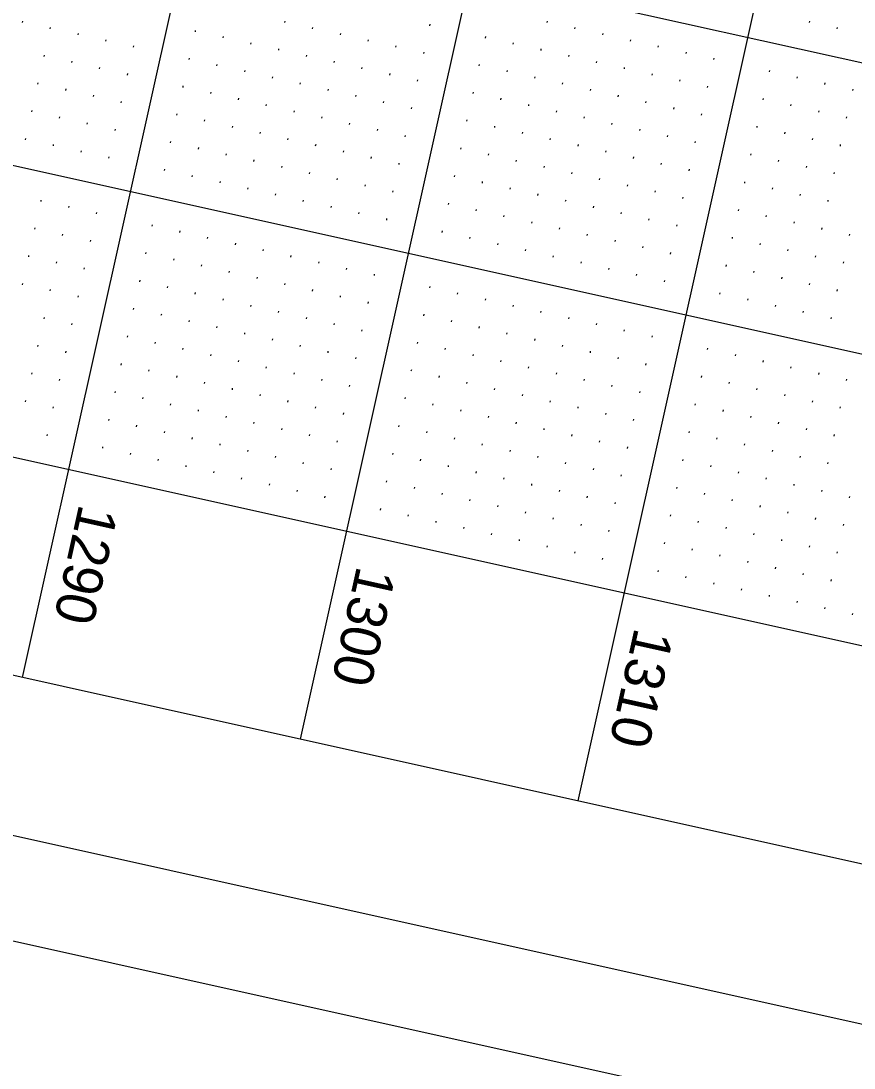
# Model space of a CAD drawing. Extents: x 2149268 to 2150830, y 142155 to 144285.
# Drawn here: x 2149571.9 to 2149718.3, y 142325.7 to 142509.8 of the extents above; entities that cross this region are included whole.
import ezdxf

# ---------------------------------------------------------------- set-up
doc = ezdxf.new("R2010")
doc.units = 0
for name, color, linetype in [('SHT_Plan_Profile_Sheet_Elev_Txt', 7, 'Continuous'), ('SHT_Plot_Shape_Full', 7, 'Continuous'), ('SHT_Plot_Shape_Half', 7, 'Continuous'), ('SHT_Profile_Grid_Major', 7, 'Continuous'), ('SHT_Profile_Grid_Minor', 7, 'Continuous'), ('SHT_Sheet_Border', 7, 'Continuous')]:
    doc.layers.add(name, color=color, linetype=linetype)

msp = doc.modelspace()

# ---------------------------------------------------------------- linework, layer by layer
at = {"layer": 'SHT_Plot_Shape_Full'}
msp.add_lwpolyline([(2150830.28, 143911.83), (2150439.58, 142154.75), (2149268.19, 142415.21), (2149658.89, 144172.3)], close=True, dxfattribs=at)
at = {"layer": 'SHT_Plot_Shape_Half'}
msp.add_lwpolyline([(2150772.24, 143840.86), (2150403.25, 142181.39), (2149329.47, 142420.15), (2149698.47, 144079.62)], close=True, dxfattribs=at)
at = {"layer": 'SHT_Profile_Grid_Major'}
for p, q in [((2149914.02, 143931.81), (2149572.16, 142394.36)), ((2149962.83, 143920.96), (2149620.97, 142383.51)), ((2150011.64, 143910.11), (2149669.77, 142372.66)), ((2149504.39, 142550.29), (2149894.85, 142463.47)), ((2149493.54, 142501.48), (2149884, 142414.66))]:
    msp.add_line(p, q, dxfattribs=at)
at = {"layer": 'SHT_Profile_Grid_Minor'}
for p, q in [((2149572.2, 142509.73), (2149572.15, 142509.48)), ((2149577.08, 142508.64), (2149577.03, 142508.4)), ((2149602.57, 142508.1), (2149602.52, 142507.85)), ((2149618.3, 142509.72), (2149618.24, 142509.48)), ((2149623.18, 142508.64), (2149623.13, 142508.39)), ((2149643.79, 142509.18), (2149643.73, 142508.93)), ((2149664.4, 142509.72), (2149664.34, 142509.47)), ((2149669.28, 142508.63), (2149669.22, 142508.39)), ((2149710.49, 142509.71), (2149710.44, 142509.47)), ((2149715.37, 142508.62), (2149715.32, 142508.38)), ((2149581.96, 142507.56), (2149581.91, 142507.31)), ((2149586.84, 142506.47), (2149586.79, 142506.23)), ((2149607.45, 142507.01), (2149607.4, 142506.77)), ((2149628.06, 142507.55), (2149628.01, 142507.31)), ((2149632.94, 142506.47), (2149632.89, 142506.22)), ((2149653.55, 142507.01), (2149653.5, 142506.76)), ((2149674.16, 142507.55), (2149674.1, 142507.3)), ((2149679.04, 142506.46), (2149678.98, 142506.22)), ((2149591.72, 142505.39), (2149591.67, 142505.14)), ((2149612.33, 142505.93), (2149612.28, 142505.68)), ((2149617.21, 142504.84), (2149617.16, 142504.6)), ((2149637.82, 142505.38), (2149637.77, 142505.14)), ((2149642.7, 142504.3), (2149642.65, 142504.05)), ((2149658.43, 142505.92), (2149658.38, 142505.68)), ((2149663.31, 142504.84), (2149663.26, 142504.59)), ((2149683.92, 142505.37), (2149683.87, 142505.13)), ((2149688.8, 142504.29), (2149688.75, 142504.05)), ((2149576, 142503.76), (2149575.94, 142503.52)), ((2149580.88, 142502.68), (2149580.82, 142502.43)), ((2149601.49, 142503.22), (2149601.43, 142502.97)), ((2149622.09, 142503.76), (2149622.04, 142503.51)), ((2149626.97, 142502.67), (2149626.92, 142502.43)), ((2149668.19, 142503.75), (2149668.14, 142503.51)), ((2149673.07, 142502.66), (2149673.02, 142502.42)), ((2149693.68, 142503.2), (2149693.63, 142502.96)), ((2149585.76, 142501.59), (2149585.7, 142501.35)), ((2149606.37, 142502.13), (2149606.31, 142501.89)), ((2149611.25, 142501.05), (2149611.19, 142500.8)), ((2149631.86, 142501.59), (2149631.8, 142501.34)), ((2149652.46, 142502.13), (2149652.41, 142501.88)), ((2149657.35, 142501.04), (2149657.29, 142500.8)), ((2149677.95, 142501.58), (2149677.9, 142501.34)), ((2149703.44, 142501.03), (2149703.39, 142500.79)), ((2149574.91, 142498.88), (2149574.86, 142498.64)), ((2149590.64, 142500.51), (2149590.58, 142500.26)), ((2149616.13, 142499.96), (2149616.07, 142499.72)), ((2149621.01, 142498.88), (2149620.95, 142498.63)), ((2149636.74, 142500.5), (2149636.68, 142500.26)), ((2149641.62, 142499.41), (2149641.56, 142499.17)), ((2149662.23, 142499.95), (2149662.17, 142499.71)), ((2149667.11, 142498.87), (2149667.05, 142498.63)), ((2149682.83, 142500.49), (2149682.78, 142500.25)), ((2149687.72, 142499.41), (2149687.66, 142499.16)), ((2149708.32, 142499.95), (2149708.27, 142499.7)), ((2149713.2, 142498.86), (2149713.15, 142498.62)), ((2149579.79, 142497.8), (2149579.74, 142497.55)), ((2149600.4, 142498.34), (2149600.35, 142498.09)), ((2149605.28, 142497.25), (2149605.23, 142497.01)), ((2149625.89, 142497.79), (2149625.84, 142497.55)), ((2149651.38, 142497.24), (2149651.32, 142497)), ((2149671.99, 142497.78), (2149671.93, 142497.54)), ((2149692.6, 142498.32), (2149692.54, 142498.08)), ((2149718.09, 142497.78), (2149718.03, 142497.53)), ((2149584.67, 142496.71), (2149584.62, 142496.47)), ((2149589.55, 142495.63), (2149589.5, 142495.38)), ((2149610.16, 142496.16), (2149610.11, 142495.92)), ((2149615.04, 142495.08), (2149614.99, 142494.84)), ((2149630.77, 142496.7), (2149630.72, 142496.46)), ((2149635.65, 142495.62), (2149635.6, 142495.38)), ((2149656.26, 142496.16), (2149656.21, 142495.91)), ((2149661.14, 142495.07), (2149661.09, 142494.83)), ((2149676.87, 142496.7), (2149676.81, 142496.45)), ((2149681.75, 142495.61), (2149681.69, 142495.37)), ((2149702.36, 142496.15), (2149702.3, 142495.91)), ((2149707.24, 142495.07), (2149707.18, 142494.82)), ((2149573.83, 142494), (2149573.77, 142493.76)), ((2149599.32, 142493.45), (2149599.26, 142493.21)), ((2149619.92, 142493.99), (2149619.87, 142493.75)), ((2149640.53, 142494.53), (2149640.48, 142494.29)), ((2149666.02, 142493.99), (2149665.97, 142493.74)), ((2149686.63, 142494.53), (2149686.58, 142494.28)), ((2149691.51, 142493.44), (2149691.46, 142493.2)), ((2149712.12, 142493.98), (2149712.06, 142493.74)), ((2149578.71, 142492.92), (2149578.65, 142492.67)), ((2149583.59, 142491.83), (2149583.53, 142491.59)), ((2149604.2, 142492.37), (2149604.14, 142492.13)), ((2149624.8, 142492.91), (2149624.75, 142492.67)), ((2149629.69, 142491.82), (2149629.63, 142491.58)), ((2149650.29, 142492.36), (2149650.24, 142492.12)), ((2149670.9, 142492.9), (2149670.85, 142492.66)), ((2149675.78, 142491.82), (2149675.73, 142491.57)), ((2149717, 142492.9), (2149716.95, 142492.65)), ((2149588.47, 142490.74), (2149588.41, 142490.5)), ((2149609.08, 142491.28), (2149609.02, 142491.04)), ((2149613.96, 142490.2), (2149613.9, 142489.95)), ((2149634.57, 142490.74), (2149634.51, 142490.49)), ((2149639.45, 142489.65), (2149639.39, 142489.41)), ((2149655.17, 142491.28), (2149655.12, 142491.03)), ((2149660.06, 142490.19), (2149660, 142489.95)), ((2149680.66, 142490.73), (2149680.61, 142490.49)), ((2149685.54, 142489.65), (2149685.49, 142489.4)), ((2149701.27, 142491.27), (2149701.22, 142491.03)), ((2149706.15, 142490.19), (2149706.1, 142489.94)), ((2149572.74, 142489.12), (2149572.69, 142488.88)), ((2149577.62, 142488.03), (2149577.57, 142487.79)), ((2149598.23, 142488.57), (2149598.18, 142488.33)), ((2149618.84, 142489.11), (2149618.78, 142488.87)), ((2149623.72, 142488.03), (2149623.66, 142487.78)), ((2149664.94, 142489.11), (2149664.88, 142488.86)), ((2149669.82, 142488.02), (2149669.76, 142487.78)), ((2149690.43, 142488.56), (2149690.37, 142488.32)), ((2149711.03, 142489.1), (2149710.98, 142488.86)), ((2149715.91, 142488.02), (2149715.86, 142487.77)), ((2149582.5, 142486.95), (2149582.45, 142486.7)), ((2149587.38, 142485.86), (2149587.33, 142485.62)), ((2149603.11, 142487.49), (2149603.06, 142487.24)), ((2149607.99, 142486.4), (2149607.94, 142486.16)), ((2149628.6, 142486.94), (2149628.55, 142486.7)), ((2149633.48, 142485.86), (2149633.43, 142485.61)), ((2149649.21, 142487.48), (2149649.15, 142487.24)), ((2149654.09, 142486.4), (2149654.03, 142486.15)), ((2149674.7, 142486.94), (2149674.64, 142486.69)), ((2149679.58, 142485.85), (2149679.52, 142485.61)), ((2149700.19, 142486.39), (2149700.13, 142486.15)), ((2149612.87, 142485.32), (2149612.82, 142485.07)), ((2149617.75, 142484.23), (2149617.7, 142483.99)), ((2149638.36, 142484.77), (2149638.31, 142484.53)), ((2149658.97, 142485.31), (2149658.92, 142485.07)), ((2149663.85, 142484.23), (2149663.8, 142483.98)), ((2149684.46, 142484.77), (2149684.4, 142484.52)), ((2149705.07, 142485.31), (2149705.01, 142485.06)), ((2149709.95, 142484.22), (2149709.89, 142483.98)), ((2149597.14, 142483.69), (2149597.09, 142483.45)), ((2149602.03, 142482.61), (2149601.97, 142482.36)), ((2149622.63, 142483.15), (2149622.58, 142482.9)), ((2149648.12, 142482.6), (2149648.07, 142482.36)), ((2149668.73, 142483.14), (2149668.68, 142482.9)), ((2149689.34, 142483.68), (2149689.29, 142483.44)), ((2149714.83, 142483.14), (2149714.78, 142482.89)), ((2149606.91, 142481.52), (2149606.85, 142481.28)), ((2149611.79, 142480.44), (2149611.73, 142480.19)), ((2149627.51, 142482.06), (2149627.46, 142481.82)), ((2149632.4, 142480.98), (2149632.34, 142480.73)), ((2149653, 142481.52), (2149652.95, 142481.27)), ((2149657.88, 142480.43), (2149657.83, 142480.19)), ((2149673.61, 142482.06), (2149673.56, 142481.81)), ((2149678.49, 142480.97), (2149678.44, 142480.73)), ((2149699.1, 142481.51), (2149699.05, 142481.27)), ((2149703.98, 142480.43), (2149703.93, 142480.18)), ((2149616.67, 142479.35), (2149616.61, 142479.11)), ((2149637.28, 142479.89), (2149637.22, 142479.65)), ((2149662.77, 142479.35), (2149662.71, 142479.1)), ((2149683.37, 142479.89), (2149683.32, 142479.64)), ((2149688.25, 142478.8), (2149688.2, 142478.56)), ((2149708.86, 142479.34), (2149708.81, 142479.1)), ((2149575.45, 142478.27), (2149575.4, 142478.03)), ((2149580.33, 142477.19), (2149580.28, 142476.94)), ((2149621.55, 142478.27), (2149621.49, 142478.02)), ((2149626.43, 142477.18), (2149626.38, 142476.94)), ((2149647.04, 142477.72), (2149646.98, 142477.48)), ((2149667.65, 142478.26), (2149667.59, 142478.02)), ((2149672.53, 142477.18), (2149672.47, 142476.93)), ((2149713.74, 142478.25), (2149713.69, 142478.01)), ((2149585.21, 142476.1), (2149585.16, 142475.86)), ((2149631.31, 142476.1), (2149631.26, 142475.85)), ((2149636.19, 142475.01), (2149636.14, 142474.77)), ((2149651.92, 142476.64), (2149651.86, 142476.39)), ((2149656.8, 142475.55), (2149656.75, 142475.31)), ((2149677.41, 142476.09), (2149677.35, 142475.85)), ((2149682.29, 142475), (2149682.23, 142474.76)), ((2149698.02, 142476.63), (2149697.96, 142476.39)), ((2149702.9, 142475.54), (2149702.84, 142475.3)), ((2149574.37, 142473.39), (2149574.31, 142473.15)), ((2149594.97, 142473.93), (2149594.92, 142473.69)), ((2149661.68, 142474.47), (2149661.63, 142474.22)), ((2149666.56, 142473.38), (2149666.51, 142473.14)), ((2149687.17, 142473.92), (2149687.12, 142473.68)), ((2149707.78, 142474.46), (2149707.72, 142474.22)), ((2149712.66, 142473.37), (2149712.6, 142473.13)), ((2149579.25, 142472.31), (2149579.19, 142472.06)), ((2149584.13, 142471.22), (2149584.07, 142470.98)), ((2149599.85, 142472.85), (2149599.8, 142472.6)), ((2149604.74, 142471.76), (2149604.68, 142471.52)), ((2149645.95, 142472.84), (2149645.9, 142472.6)), ((2149650.83, 142471.76), (2149650.78, 142471.51)), ((2149671.44, 142472.29), (2149671.39, 142472.05)), ((2149676.32, 142471.21), (2149676.27, 142470.97)), ((2149696.93, 142471.75), (2149696.88, 142471.51)), ((2149717.54, 142472.29), (2149717.49, 142472.04)), ((2149609.62, 142470.68), (2149609.56, 142470.43)), ((2149614.5, 142469.59), (2149614.44, 142469.35)), ((2149655.71, 142470.67), (2149655.66, 142470.43)), ((2149660.59, 142469.58), (2149660.54, 142469.34)), ((2149681.2, 142470.12), (2149681.15, 142469.88)), ((2149701.81, 142470.66), (2149701.76, 142470.42)), ((2149706.69, 142469.58), (2149706.64, 142469.33)), ((2149573.28, 142468.51), (2149573.23, 142468.27)), ((2149593.89, 142469.05), (2149593.83, 142468.81)), ((2149598.77, 142467.97), (2149598.72, 142467.72)), ((2149619.38, 142468.51), (2149619.32, 142468.26)), ((2149665.48, 142468.5), (2149665.42, 142468.26)), ((2149686.08, 142469.04), (2149686.03, 142468.79)), ((2149711.57, 142468.49), (2149711.52, 142468.25)), ((2149578.16, 142467.43), (2149578.11, 142467.18)), ((2149583.04, 142466.34), (2149582.99, 142466.1)), ((2149603.65, 142466.88), (2149603.6, 142466.64)), ((2149608.53, 142465.79), (2149608.48, 142465.55)), ((2149624.26, 142467.42), (2149624.2, 142467.18)), ((2149629.14, 142466.33), (2149629.09, 142466.09)), ((2149670.36, 142467.41), (2149670.3, 142467.17)), ((2149675.24, 142466.33), (2149675.18, 142466.08)), ((2149695.85, 142466.87), (2149695.79, 142466.62)), ((2149700.73, 142465.78), (2149700.67, 142465.54)), ((2149716.45, 142467.41), (2149716.4, 142467.16)), ((2149592.8, 142464.17), (2149592.75, 142463.93)), ((2149613.41, 142464.71), (2149613.36, 142464.47)), ((2149634.02, 142465.25), (2149633.97, 142465.01)), ((2149680.12, 142465.24), (2149680.06, 142465)), ((2149685, 142464.16), (2149684.94, 142463.91)), ((2149705.61, 142464.7), (2149705.55, 142464.45)), ((2149572.19, 142463.63), (2149572.14, 142463.39)), ((2149577.08, 142462.54), (2149577.02, 142462.3)), ((2149597.68, 142463.08), (2149597.63, 142462.84)), ((2149602.57, 142462), (2149602.51, 142461.76)), ((2149618.29, 142463.62), (2149618.24, 142463.38)), ((2149623.17, 142462.54), (2149623.12, 142462.29)), ((2149643.78, 142463.08), (2149643.73, 142462.83)), ((2149648.66, 142461.99), (2149648.61, 142461.75)), ((2149694.76, 142461.99), (2149694.71, 142461.74)), ((2149710.49, 142463.61), (2149710.43, 142463.37)), ((2149715.37, 142462.53), (2149715.31, 142462.28)), ((2149581.96, 142461.46), (2149581.9, 142461.22)), ((2149607.45, 142460.91), (2149607.39, 142460.67)), ((2149628.05, 142461.45), (2149628, 142461.21)), ((2149632.94, 142460.37), (2149632.88, 142460.12)), ((2149653.54, 142460.91), (2149653.49, 142460.66)), ((2149699.64, 142460.9), (2149699.59, 142460.66)), ((2149591.72, 142459.29), (2149591.66, 142459.05)), ((2149612.33, 142459.83), (2149612.27, 142459.58)), ((2149617.21, 142458.74), (2149617.15, 142458.5)), ((2149658.42, 142459.82), (2149658.37, 142459.58)), ((2149663.31, 142458.74), (2149663.25, 142458.49)), ((2149704.52, 142459.82), (2149704.47, 142459.57)), ((2149709.4, 142458.73), (2149709.35, 142458.49)), ((2149575.99, 142457.66), (2149575.94, 142457.42)), ((2149580.87, 142456.58), (2149580.82, 142456.33)), ((2149596.6, 142458.2), (2149596.54, 142457.96)), ((2149601.48, 142457.12), (2149601.43, 142456.87)), ((2149622.09, 142457.66), (2149622.03, 142457.41)), ((2149626.97, 142456.57), (2149626.91, 142456.33)), ((2149642.7, 142458.2), (2149642.64, 142457.95)), ((2149647.58, 142457.11), (2149647.52, 142456.87)), ((2149668.19, 142457.65), (2149668.13, 142457.41)), ((2149673.07, 142456.57), (2149673.01, 142456.32)), ((2149714.28, 142457.65), (2149714.23, 142457.4)), ((2149606.36, 142456.03), (2149606.31, 142455.79)), ((2149611.24, 142454.95), (2149611.19, 142454.7)), ((2149631.85, 142455.49), (2149631.8, 142455.24)), ((2149652.46, 142456.03), (2149652.4, 142455.78)), ((2149657.34, 142454.94), (2149657.28, 142454.7)), ((2149677.95, 142455.48), (2149677.89, 142455.24)), ((2149574.91, 142452.78), (2149574.85, 142452.54)), ((2149590.63, 142454.41), (2149590.58, 142454.16)), ((2149595.51, 142453.32), (2149595.46, 142453.08)), ((2149616.12, 142453.86), (2149616.07, 142453.62)), ((2149621, 142452.78), (2149620.95, 142452.53)), ((2149641.61, 142453.32), (2149641.56, 142453.07)), ((2149662.22, 142453.86), (2149662.17, 142453.61)), ((2149667.1, 142452.77), (2149667.05, 142452.53)), ((2149682.83, 142454.4), (2149682.77, 142454.15)), ((2149579.79, 142451.7), (2149579.73, 142451.45)), ((2149600.39, 142452.24), (2149600.34, 142451.99)), ((2149605.28, 142451.15), (2149605.22, 142450.91)), ((2149625.88, 142451.69), (2149625.83, 142451.45)), ((2149646.49, 142452.23), (2149646.44, 142451.99)), ((2149651.37, 142451.15), (2149651.32, 142450.9)), ((2149671.98, 142451.69), (2149671.93, 142451.44)), ((2149692.59, 142452.23), (2149692.54, 142451.98)), ((2149697.47, 142451.14), (2149697.42, 142450.9)), ((2149589.55, 142449.53), (2149589.49, 142449.28)), ((2149610.16, 142450.07), (2149610.1, 142449.82)), ((2149630.76, 142450.61), (2149630.71, 142450.36)), ((2149656.25, 142450.06), (2149656.2, 142449.82)), ((2149676.86, 142450.6), (2149676.81, 142450.36)), ((2149681.74, 142449.52), (2149681.69, 142449.27)), ((2149702.35, 142450.06), (2149702.3, 142449.81)), ((2149573.82, 142447.9), (2149573.77, 142447.66)), ((2149594.43, 142448.44), (2149594.37, 142448.2)), ((2149599.31, 142447.36), (2149599.25, 142447.11)), ((2149615.04, 142448.98), (2149614.98, 142448.74)), ((2149619.92, 142447.9), (2149619.86, 142447.65)), ((2149640.53, 142448.44), (2149640.47, 142448.19)), ((2149645.41, 142447.35), (2149645.35, 142447.11)), ((2149661.13, 142448.98), (2149661.08, 142448.73)), ((2149666.02, 142447.89), (2149665.96, 142447.65)), ((2149691.5, 142447.35), (2149691.45, 142447.1)), ((2149707.23, 142448.97), (2149707.18, 142448.73)), ((2149712.11, 142447.88), (2149712.06, 142447.64)), ((2149578.7, 142446.82), (2149578.65, 142446.57)), ((2149604.19, 142446.27), (2149604.14, 142446.03)), ((2149624.8, 142446.81), (2149624.74, 142446.57)), ((2149629.68, 142445.73), (2149629.62, 142445.48)), ((2149650.29, 142446.27), (2149650.23, 142446.02)), ((2149670.9, 142446.81), (2149670.84, 142446.56)), ((2149675.78, 142445.72), (2149675.72, 142445.48)), ((2149696.39, 142446.26), (2149696.33, 142446.02)), ((2149716.99, 142446.8), (2149716.94, 142446.56)), ((2149588.46, 142444.65), (2149588.41, 142444.4)), ((2149593.34, 142443.56), (2149593.29, 142443.32)), ((2149609.07, 142445.19), (2149609.02, 142444.94)), ((2149613.95, 142444.1), (2149613.9, 142443.86)), ((2149639.44, 142443.56), (2149639.39, 142443.31)), ((2149655.17, 142445.18), (2149655.11, 142444.94)), ((2149660.05, 142444.1), (2149660, 142443.85)), ((2149680.66, 142444.63), (2149680.6, 142444.39)), ((2149701.27, 142445.17), (2149701.21, 142444.93)), ((2149706.15, 142444.09), (2149706.09, 142443.85)), ((2149572.73, 142443.02), (2149572.68, 142442.78)), ((2149577.62, 142441.94), (2149577.56, 142441.69)), ((2149598.22, 142442.48), (2149598.17, 142442.23)), ((2149618.83, 142443.02), (2149618.78, 142442.77)), ((2149623.71, 142441.93), (2149623.66, 142441.69)), ((2149644.32, 142442.47), (2149644.27, 142442.23)), ((2149664.93, 142443.01), (2149664.88, 142442.77)), ((2149669.81, 142441.92), (2149669.76, 142441.68)), ((2149690.42, 142442.46), (2149690.37, 142442.22)), ((2149711.03, 142443), (2149710.97, 142442.76)), ((2149715.91, 142441.92), (2149715.85, 142441.67)), ((2149603.1, 142441.39), (2149603.05, 142441.15)), ((2149607.99, 142440.31), (2149607.93, 142440.06)), ((2149628.59, 142440.85), (2149628.54, 142440.6)), ((2149649.2, 142441.38), (2149649.15, 142441.14)), ((2149654.08, 142440.3), (2149654.03, 142440.06)), ((2149674.69, 142440.84), (2149674.64, 142440.6)), ((2149695.3, 142441.38), (2149695.25, 142441.13)), ((2149700.18, 142440.29), (2149700.13, 142440.05)), ((2149587.38, 142439.77), (2149587.32, 142439.52)), ((2149592.26, 142438.68), (2149592.2, 142438.44)), ((2149612.87, 142439.22), (2149612.81, 142438.98)), ((2149617.75, 142438.14), (2149617.69, 142437.89)), ((2149638.36, 142438.67), (2149638.3, 142438.43)), ((2149658.96, 142439.21), (2149658.91, 142438.97)), ((2149663.84, 142438.13), (2149663.79, 142437.89)), ((2149679.57, 142439.75), (2149679.52, 142439.51)), ((2149705.06, 142439.21), (2149705.01, 142438.96)), ((2149709.94, 142438.12), (2149709.89, 142437.88)), ((2149576.53, 142437.06), (2149576.48, 142436.81)), ((2149597.14, 142437.6), (2149597.08, 142437.35)), ((2149602.02, 142436.51), (2149601.97, 142436.27)), ((2149622.63, 142437.05), (2149622.57, 142436.81)), ((2149643.24, 142437.59), (2149643.18, 142437.35)), ((2149648.12, 142436.5), (2149648.06, 142436.26)), ((2149668.73, 142437.04), (2149668.67, 142436.8)), ((2149689.33, 142437.58), (2149689.28, 142437.34)), ((2149694.21, 142436.5), (2149694.16, 142436.25)), ((2149714.82, 142437.04), (2149714.77, 142436.79)), ((2149586.29, 142434.89), (2149586.24, 142434.64)), ((2149606.9, 142435.42), (2149606.85, 142435.18)), ((2149611.78, 142434.34), (2149611.73, 142434.1)), ((2149627.51, 142435.96), (2149627.45, 142435.72)), ((2149653, 142435.42), (2149652.94, 142435.17)), ((2149657.88, 142434.33), (2149657.82, 142434.09)), ((2149673.61, 142435.96), (2149673.55, 142435.71)), ((2149678.49, 142434.87), (2149678.43, 142434.63)), ((2149699.1, 142435.41), (2149699.04, 142435.17)), ((2149703.98, 142434.33), (2149703.92, 142434.08)), ((2149591.17, 142433.8), (2149591.12, 142433.56)), ((2149596.05, 142432.71), (2149596, 142432.47)), ((2149616.66, 142433.25), (2149616.61, 142433.01)), ((2149637.27, 142433.79), (2149637.22, 142433.55)), ((2149642.15, 142432.71), (2149642.1, 142432.46)), ((2149662.76, 142433.25), (2149662.71, 142433)), ((2149688.25, 142432.7), (2149688.19, 142432.46)), ((2149708.86, 142433.24), (2149708.8, 142433)), ((2149600.93, 142431.63), (2149600.88, 142431.39)), ((2149621.54, 142432.17), (2149621.49, 142431.92)), ((2149626.42, 142431.08), (2149626.37, 142430.84)), ((2149647.03, 142431.62), (2149646.98, 142431.38)), ((2149667.64, 142432.16), (2149667.59, 142431.92)), ((2149672.52, 142431.08), (2149672.47, 142430.83)), ((2149693.13, 142431.62), (2149693.08, 142431.37)), ((2149713.74, 142432.16), (2149713.68, 142431.91)), ((2149605.81, 142430.54), (2149605.76, 142430.3)), ((2149610.7, 142429.46), (2149610.64, 142429.21)), ((2149636.19, 142428.91), (2149636.13, 142428.67)), ((2149651.91, 142430.54), (2149651.86, 142430.29)), ((2149656.79, 142429.45), (2149656.74, 142429.21)), ((2149677.4, 142429.99), (2149677.35, 142429.75)), ((2149698.01, 142430.53), (2149697.96, 142430.29)), ((2149702.89, 142429.45), (2149702.84, 142429.2)), ((2149615.58, 142428.37), (2149615.52, 142428.13)), ((2149620.46, 142427.29), (2149620.4, 142427.04)), ((2149641.07, 142427.83), (2149641.01, 142427.58)), ((2149661.67, 142428.37), (2149661.62, 142428.12)), ((2149666.56, 142427.28), (2149666.5, 142427.04)), ((2149687.16, 142427.82), (2149687.11, 142427.58)), ((2149707.77, 142428.36), (2149707.72, 142428.12)), ((2149712.65, 142427.28), (2149712.6, 142427.03)), ((2149625.34, 142426.2), (2149625.28, 142425.96)), ((2149645.95, 142426.74), (2149645.89, 142426.5)), ((2149650.83, 142425.66), (2149650.77, 142425.41)), ((2149671.44, 142426.2), (2149671.38, 142425.95)), ((2149676.32, 142425.11), (2149676.26, 142424.87)), ((2149692.04, 142426.74), (2149691.99, 142426.49)), ((2149696.93, 142425.65), (2149696.87, 142425.41)), ((2149717.53, 142426.19), (2149717.48, 142425.95)), ((2149635.1, 142424.03), (2149635.05, 142423.79)), ((2149655.71, 142424.57), (2149655.65, 142424.33)), ((2149660.59, 142423.49), (2149660.53, 142423.24)), ((2149701.81, 142424.57), (2149701.75, 142424.32)), ((2149706.69, 142423.48), (2149706.63, 142423.24)), ((2149639.98, 142422.95), (2149639.93, 142422.7)), ((2149644.86, 142421.86), (2149644.81, 142421.62)), ((2149665.47, 142422.4), (2149665.42, 142422.16)), ((2149686.08, 142422.94), (2149686.02, 142422.7)), ((2149690.96, 142421.86), (2149690.9, 142421.61)), ((2149711.57, 142422.4), (2149711.51, 142422.15)), ((2149649.74, 142420.78), (2149649.69, 142420.53)), ((2149654.62, 142419.69), (2149654.57, 142419.45)), ((2149670.35, 142421.32), (2149670.3, 142421.07)), ((2149675.23, 142420.23), (2149675.18, 142419.99)), ((2149695.84, 142420.77), (2149695.79, 142420.53)), ((2149700.72, 142419.69), (2149700.67, 142419.44)), ((2149716.45, 142421.31), (2149716.39, 142421.07)), ((2149659.5, 142418.61), (2149659.45, 142418.36)), ((2149684.99, 142418.06), (2149684.94, 142417.82)), ((2149705.6, 142418.6), (2149705.55, 142418.36)), ((2149664.38, 142417.52), (2149664.33, 142417.28)), ((2149669.27, 142416.44), (2149669.21, 142416.19)), ((2149689.87, 142416.98), (2149689.82, 142416.73)), ((2149710.48, 142417.51), (2149710.43, 142417.27)), ((2149715.36, 142416.43), (2149715.31, 142416.19)), ((2149674.15, 142415.35), (2149674.09, 142415.11)), ((2149694.75, 142415.89), (2149694.7, 142415.65)), ((2149699.64, 142414.8), (2149699.58, 142414.56)), ((2149683.91, 142413.18), (2149683.85, 142412.94)), ((2149704.52, 142413.72), (2149704.46, 142413.48)), ((2149709.4, 142412.63), (2149709.34, 142412.39)), ((2149688.79, 142412.09), (2149688.73, 142411.85)), ((2149693.67, 142411.01), (2149693.62, 142410.76)), ((2149714.28, 142411.55), (2149714.22, 142411.3)), ((2149698.55, 142409.92), (2149698.5, 142409.68)), ((2149703.43, 142408.84), (2149703.38, 142408.59)), ((2149708.31, 142407.75), (2149708.26, 142407.51)), ((2149713.19, 142406.67), (2149713.14, 142406.42)), ((2149718.07, 142405.58), (2149718.02, 142405.34))]:
    msp.add_line(p, q, dxfattribs=at)
at = {"layer": 'SHT_Sheet_Border'}
msp.add_line((2149409.47, 142468.95), (2149873.15, 142365.85), dxfattribs=at)
msp.add_lwpolyline([(2150726.67, 143751.11), (2150384.81, 142213.66), (2149359.84, 142441.57), (2149701.71, 143979.02)], close=True, dxfattribs=at)

# ---------------------------------------------------------------- texts
at = {"layer": 'SHT_Plan_Profile_Sheet_Elev_Txt'}
for s, p in [('1290', (2149582.21, 142425.02)), ('1300', (2149631.02, 142414.16)), ('1310', (2149679.82, 142403.31))]:
    msp.add_text(s, height=7, rotation=257.4638, dxfattribs=at).set_placement(p)

doc.saveas('drawing.dxf')
